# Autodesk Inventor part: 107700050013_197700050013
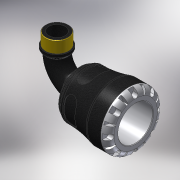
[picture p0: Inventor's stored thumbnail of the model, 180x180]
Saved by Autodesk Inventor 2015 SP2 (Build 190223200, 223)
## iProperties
Created: 2016-12
Part Number: 107700050013_197700050013
Material: PVC-Piping
Description: PLASSON 90° ELBOW WITH MALE INTEGRAL BRASS 50X1.1/4" SERIES 1
Document SubType Name: Modeling
Designer: KIM
Mass: 664.223 g
Surface Area: 733.008 cm^2
Volume: 474.445 cm^3
Density: 1.4 g/cm^3
Appearance: Black Cast
Author: KIM
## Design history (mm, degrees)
derived "1077.ipt"
feature "Solid1::1077.ipt"
tag "TaggingFeature1"
body "Solid1"
other parameters: "d1" = 33.18, "d3" = 62.5, "d4" = 85, "d8" = 72.25, "d13" = 9, "d14" = 9, "d15" = 0, "d17" = 360 deg, "d19" = 8 deg, "d20" = 1, "d21" = 1, "d22" = 8 deg, "d24" = 0, "d26" = 360 deg, "d33" = 8.5, "d43" = 66.3, "d51" = 0.85, "d54" = 17.5, "d55" = 11, "d57" = 17.64, "d58" = 0, "d74" = 0, "d78" = 79, "d82" = 1, "d115" = 360 deg, "d207" = 90 deg, "d228" = 14.875, "d247" = 1.7, "d248" = 4.74, "d268" = 39.7375, "d269" = 4.74, "d270" = 116, "d276" = 41.91, "d277" = 21, "d278" = 46.101, "d279" = 68, "d280" = 27.3, "d281" = 6.2865, "d283" = 37.719, "d286" = 0, "d287" = 0, "d288" = 29.337, "d290" = 14.2905, "d292" = 30 deg, "d294" = 4.191, "d296" = 30 deg, "E_" = 85, "l_" = 79, "A_" = 116, "A_1" = 68, "l_2" = 21, "R_" = 41.91, "d9" = 11.25, "d11" = 85, "d12" = 62.5, "d289" = 29.337
